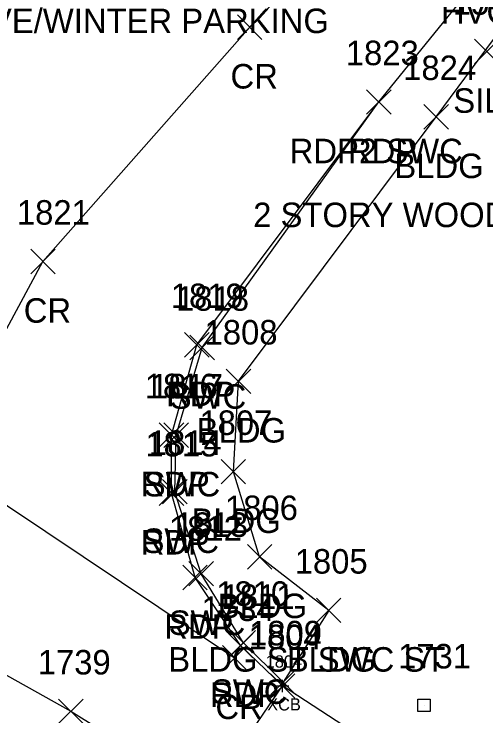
# Model space of a CAD drawing. Extents: x 1657482 to 1661439, y 647981 to 649041.
# Drawn here: x 1659969 to 1660007.4, y 648047.4 to 648104.7 of the extents above; entities that cross this region are included whole.
import ezdxf

# ---------------------------------------------------------------- set-up
doc = ezdxf.new("R2010")
doc.units = 0
for name, color, linetype in [('B_A', 7, 'Continuous'), ('B_I', 7, 'Continuous'), ('B_TIC', 7, 'Continuous'), ('BDC', 7, 'Continuous'), ('C_A', 7, 'Continuous'), ('C_I', 7, 'Continuous'), ('CPBM', 7, 'Continuous'), ('L_A', 7, 'Continuous'), ('L_C', 7, 'Continuous'), ('L_I', 7, 'Continuous'), ('L_TIC', 7, 'Continuous'), ('LBC', 7, 'Continuous'), ('P_A', 7, 'Continuous'), ('P_I', 7, 'Continuous'), ('P_TIC', 7, 'Continuous'), ('PET', 7, 'Continuous'), ('PRC', 7, 'Continuous'), ('R_A', 7, 'Continuous'), ('R_I', 7, 'Continuous'), ('R_TIC', 7, 'Continuous'), ('RSW', 7, 'Continuous'), ('S_C', 7, 'Continuous')]:
    doc.layers.add(name, color=color, linetype=linetype)

msp = doc.modelspace()

# ---------------------------------------------------------------- linework, layer by layer
at = {"layer": 'B_TIC'}
msp.add_line((1659990.858, 648049.845), (1659990.933, 648049.845), dxfattribs=at)
for points in [[(1659990.854, 648049.345), (1659990.854, 648050.345)], [(1659990.354, 648049.845), (1659991.354, 648049.845)]]:
    msp.add_lwpolyline(points, dxfattribs=at)
at = {"layer": 'BDC'}
msp.add_lwpolyline([(1660042.45, 648016.386), (1660019.758, 648030.97), (1659990.854, 648049.845)], dxfattribs=at)
at = {"layer": 'CPBM'}
for p, q in [((1660001.884, 648047.772), (1660001.884, 648048.772)), ((1660001.884, 648048.772), (1660002.884, 648048.772)), ((1660002.884, 648048.772), (1660002.884, 648047.772)), ((1660002.387, 648048.273), (1660002.387, 648048.273)), ((1660002.387, 648048.273), (1660002.387, 648048.273)), ((1660002.884, 648047.772), (1660001.884, 648047.772))]:
    msp.add_line(p, q, dxfattribs=at)
at = {"layer": 'L_TIC'}
for points in [[(1660006.504, 648100.608), (1660008.504, 648102.608)], [(1660008.504, 648100.608), (1660006.504, 648102.608)], [(1660002.372, 648095.281), (1660004.372, 648097.281)], [(1660004.372, 648095.281), (1660002.372, 648097.281)], [(1659986.259, 648073.705), (1659988.259, 648075.705)], [(1659988.259, 648073.705), (1659986.259, 648075.705)], [(1659985.835, 648066.326), (1659987.835, 648068.326)], [(1659987.835, 648066.326), (1659985.835, 648068.326)], [(1659987.977, 648059.381), (1659989.977, 648061.381)], [(1659989.977, 648059.381), (1659987.977, 648061.381)], [(1659993.606, 648055.013), (1659995.606, 648057.013)], [(1659995.606, 648055.013), (1659993.606, 648057.013)]]:
    msp.add_lwpolyline(points, dxfattribs=at)
at = {"layer": 'LBC'}
msp.add_lwpolyline([(1659994.606, 648056.013), (1659988.977, 648060.381), (1659986.835, 648067.326), (1659987.259, 648074.705), (1660003.372, 648096.281), (1660014.063, 648110.734), (1660016.456, 648113.864), (1660022.1, 648121.464), (1660021.576, 648122.015), (1660033.225, 648132.214), (1660046.038, 648142.625), (1660053.165, 648148.472), (1660058.192, 648152.49), (1660064.876, 648145.19)], dxfattribs=at)
at = {"layer": 'P_TIC'}
for points in [[(1659987.169, 648102.589), (1659989.169, 648104.589)], [(1659989.169, 648102.589), (1659987.169, 648104.589)], [(1659997.695, 648096.495), (1659999.695, 648098.495)], [(1659999.695, 648096.495), (1659997.695, 648098.495)], [(1659970.311, 648083.482), (1659972.311, 648085.482)], [(1659972.311, 648083.482), (1659970.311, 648085.482)], [(1659982.864, 648076.674), (1659984.864, 648078.674)], [(1659984.864, 648076.674), (1659982.864, 648078.674)], [(1659980.786, 648069.317), (1659982.786, 648071.317)], [(1659982.786, 648069.317), (1659980.786, 648071.317)], [(1659980.789, 648064.569), (1659982.789, 648066.569)], [(1659982.789, 648064.569), (1659980.789, 648066.569)], [(1659982.709, 648057.695), (1659984.709, 648059.695)], [(1659984.709, 648057.695), (1659982.709, 648059.695)], [(1659986.428, 648052.134), (1659988.428, 648054.134)], [(1659988.428, 648052.134), (1659986.428, 648054.134)], [(1659985.94, 648051.146), (1659987.94, 648053.146)], [(1659987.94, 648051.146), (1659985.94, 648053.146)], [(1659989.854, 648048.845), (1659991.854, 648050.845)], [(1659991.854, 648048.845), (1659989.854, 648050.845)], [(1659972.585, 648046.782), (1659974.585, 648048.782)], [(1659974.585, 648046.782), (1659972.585, 648048.782)]]:
    msp.add_lwpolyline(points, dxfattribs=at)
at = {"layer": 'PET'}
msp.add_lwpolyline([(1659863.28, 648081.701), (1659868.598, 648080.447), (1659876.948, 648078.161), (1659883.344, 648076.024), (1659889.16, 648073.962), (1659894.185, 648071.763), (1659897.898, 648070.646), (1659905.34, 648067.906), (1659912.798, 648065.014), (1659924.735, 648059.408), (1659938.824, 648053.114), (1659959.475, 648042.397), (1659969.15, 648037.003), (1659978.866, 648031.627), (1659984.71, 648040.852), (1659990.854, 648049.845), (1659987.428, 648053.134), (1659983.709, 648058.695), (1659981.789, 648065.569), (1659981.786, 648070.317), (1659983.864, 648077.674), (1659998.695, 648097.495), (1660020.131, 648123.934)], dxfattribs=at)
at = {"layer": 'PRC'}
for points in [[(1659963.459, 648069.889), (1659971.311, 648084.482), (1659988.169, 648103.589), (1660012.915, 648129.083), (1660023.122, 648141.511)], [(1659891.684, 648086.345), (1659903.341, 648081.608), (1659918.7, 648074.839), (1659936.602, 648066.916), (1659955.342, 648057.99), (1659973.585, 648047.782), (1659984.71, 648040.852)], [(1659938.953, 648083.445), (1659950.975, 648075.865), (1659965.344, 648066.57), (1659986.94, 648052.146)]]:
    msp.add_lwpolyline(points, dxfattribs=at)
at = {"layer": 'R_TIC'}
for points in [[(1659997.695, 648096.495), (1659999.695, 648098.495)], [(1659999.695, 648096.495), (1659997.695, 648098.495)], [(1659983.287, 648076.46), (1659985.287, 648078.46)], [(1659985.287, 648076.46), (1659983.287, 648078.46)], [(1659981.167, 648069.309), (1659983.167, 648071.309)], [(1659983.167, 648069.309), (1659981.167, 648071.309)], [(1659981.067, 648064.694), (1659983.067, 648066.694)], [(1659983.067, 648064.694), (1659981.067, 648066.694)], [(1659983.204, 648058.004), (1659985.204, 648060.004)], [(1659985.204, 648058.004), (1659983.204, 648060.004)], [(1659993.606, 648055.013), (1659995.606, 648057.013)], [(1659995.606, 648055.013), (1659993.606, 648057.013)], [(1659986.644, 648052.383), (1659988.644, 648054.383)], [(1659988.644, 648052.383), (1659986.644, 648054.383)], [(1659989.895, 648049.159), (1659991.895, 648051.159)], [(1659991.895, 648049.159), (1659989.895, 648051.159)]]:
    msp.add_lwpolyline(points, dxfattribs=at)
at = {"layer": 'RSW'}
msp.add_lwpolyline([(1659994.606, 648056.013), (1659990.895, 648050.159), (1659987.644, 648053.383), (1659984.204, 648059.004), (1659982.067, 648065.694), (1659982.167, 648070.309), (1659984.287, 648077.46), (1659998.695, 648097.495)], dxfattribs=at)

# ---------------------------------------------------------------- texts
at = {"layer": 'B_A'}
msp.add_text('XCB', height=1, dxfattribs=at).set_placement((1659989.59, 648047.845))
at = {"layer": 'B_I'}
msp.add_text('1804', height=1, dxfattribs=at).set_placement((1659989.468, 648051.345))
at = {"layer": 'C_A'}
msp.add_text('HVCTRL', height=2, dxfattribs=at).set_placement((1660003.755, 648103.881))
at = {"layer": 'C_I'}
msp.add_text('1731', height=2, dxfattribs=at).set_placement((1660000.261, 648051.273))
at = {"layer": 'L_A'}
for s, p in [('SILL', (1660004.764, 648096.608)), ('BLDG', (1659999.963, 648091.281)), ('BLDG', (1659983.849, 648069.705)), ('BLDG', (1659983.426, 648062.326)), ('BLDG', (1659985.567, 648055.381)), ('BLDG', (1659991.197, 648051.013))]:
    msp.add_text(s, height=2, dxfattribs=at).set_placement(p)
at = {"layer": 'L_C'}
msp.add_text('2 STORY WOOD #20', height=2, dxfattribs=at).set_placement((1659988.451, 648087.281))
at = {"layer": 'L_I'}
for s, p in [('1540', (1660004.725, 648104.608)), ('1824', (1660000.679, 648099.281)), ('1808', (1659984.487, 648077.705)), ('1807', (1659984.064, 648070.326)), ('1806', (1659986.15, 648063.381)), ('1805', (1659991.835, 648059.013))]:
    msp.add_text(s, height=2, dxfattribs=at).set_placement(p)
at = {"layer": 'P_A'}
for s, p in [('CR', (1659986.602, 648098.589)), ('RDP', (1659996.183, 648092.495)), ('CR', (1659969.744, 648079.482)), ('RDP', (1659981.352, 648072.674)), ('RDP', (1659979.274, 648065.317)), ('RDP', (1659979.277, 648060.569)), ('RDP', (1659981.197, 648053.695)), ('RDP', (1659984.916, 648048.134)), ('CR', (1659985.373, 648047.146))]:
    msp.add_text(s, height=2, dxfattribs=at).set_placement(p)
at = {"layer": 'P_I'}
for s, p in [('1823', (1659996.002, 648100.495)), ('1821', (1659969.185, 648087.482)), ('1819', (1659981.731, 648080.674)), ('1816', (1659979.605, 648073.317)), ('1815', (1659979.663, 648068.569)), ('1812', (1659981.583, 648061.695)), ('1811', (1659985.869, 648056.134)), ('1734', (1659984.247, 648055.146)), ('1804', (1659988.083, 648052.845)), ('1739', (1659970.885, 648050.782))]:
    msp.add_text(s, height=2, dxfattribs=at).set_placement(p)
at = {"layer": 'R_A'}
for s, p in [('RDP2 SWC', (1659991.427, 648092.495)), ('SWC', (1659981.65, 648072.46)), ('SWC', (1659979.529, 648065.309)), ('SWC', (1659979.43, 648060.694)), ('SWC', (1659981.567, 648054.004)), ('BLDG ST SWC ST', (1659981.528, 648051.013)), ('SWC', (1659985.006, 648048.383))]:
    msp.add_text(s, height=2, dxfattribs=at).set_placement(p)
at = {"layer": 'R_I'}
for s, p in [('1823', (1659996.002, 648100.495)), ('1818', (1659982.162, 648080.46)), ('1817', (1659980.041, 648073.309)), ('1814', (1659979.942, 648068.694)), ('1813', (1659982.079, 648062.004)), ('1805', (1659991.835, 648059.013)), ('1810', (1659985.432, 648056.383)), ('1809', (1659988.116, 648053.159))]:
    msp.add_text(s, height=2, dxfattribs=at).set_placement(p)
at = {"layer": 'S_C'}
msp.add_text('WARNING CURVE/WINTER PARKING', height=2, dxfattribs=at).set_placement((1659947.525, 648103.111))

doc.saveas('drawing.dxf')
